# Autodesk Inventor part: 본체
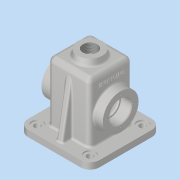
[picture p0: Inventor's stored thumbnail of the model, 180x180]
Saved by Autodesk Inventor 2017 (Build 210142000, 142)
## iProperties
Part Number: 본체
Material: 알루미늄 6061
Document SubType Name: Modeling
Designer: MRC
Density: 2.7 g/cm^3
Appearance: 알루미늄 - 평지
Mass: 753.623 g
Surface Area: 864.209 cm^2
Volume: 279.12 cm^3
Author: MRC
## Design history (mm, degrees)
sketch "스케치1"
  geometry: L1 (-34, 53)-(34, 53); L2 (34, 53)-(34, -52); L3 (34, -52)-(-34, -52); L4 (-34, -52)-(-34, 53); 2 further points
  constraints: 8 end point, 2 parallel, 1 horizontal, 1 midpoint, 1 perpendicular, 1 vertical alignment
  dimensions: "d0" = 52 distance from line of L3 point (0, 0); "d1" = 105 distance of L3.end L1.start; "d2" = 68 distance of L1.start L1.end
extrude "돌출1" new body sketch "스케치1" stored distance "d3" = 68; taper "d4" = 0 deg
fillet "모깎기1" dims "d5" = 8
fillet "모깎기2" dims "d6" = 8
feature "쉘1" dims "d7" = 5
sketch "스케치3"
  geometry: C1 r 28.5 at (26, 52); 1 further point
  constraints: 1 centre point, 1 coincident
  dimensions: "d8" = 57 diameter of C1
extrude "돌출2" join sketch "스케치3" distance "d9" = 15; taper "d11" = 0 deg; dims "d10" = 3, "d12" = 0
hole "구멍1" diameter "d15" = 30; stored, may be unused: countersink angle "d19" = 90 deg, drill point angle "d21" = 118 deg; dims "d13" = 10, "d14" = 10, "d16" = 6, "d17" = 35, "d18" = 17, "d20" = 30
sketch "스케치4"
  geometry: C1 r 17.5 at (0, 0) reference; 1 further point
  constraints: 1 vertical alignment
  dimensions: "d22" = 22 distance of C1.centre point (0, 22)
hole "구멍2" sketch "스케치4" at (0, 22) diameter "d23" = 3.242; stored, may be unused: countersink angle "d27" = 90 deg, drill point angle "d29" = 118 deg; dims "d24" = 8, "d25" = 35, "d26" = 17, "d28" = 10
sketch "스케치6"
  geometry: L1 (-8, 60)-(-8, 8) reference; L2 (52, 0)-(0, 0) reference; L3 (60, 60)-(60, 8) reference; L4 (0, 68)-(52, 68) reference; L5 (83, -23)-(-31, -23); L6 (-31, -23)-(-31, 91); L7 (-31, 91)-(83, 91); L8 (83, 91)-(83, -23); L9 (83, -23)-(-31, 91); L10 (-31, -23)-(83, 91); A1 r 8 centre (0, 60) between (0, 68) and (-8, 60) reference; A2 r 8 centre (0, 8) between (-8, 8) and (0, 0) reference; A3 r 8 centre (52, 8) between (52, 0) and (60, 8) reference; A4 r 8 centre (52, 60) between (60, 60) and (52, 68) reference; 1 further point
  constraints: 12 end point, 2 midpoint, 2 parallel, 1 horizontal, 1 perpendicular
  dimensions: "d45" = 114 distance of L6.end L7.end; "d46" = 114 distance of L5.end L6.end
extrude "돌출4" join sketch "스케치6" distance "d47" = 10; taper "d48" = 0 deg
fillet "모깎기3" dims "d49" = 15
sketch "스케치7"
  geometry: A1 r 15 centre (-16, 8) between (-16, 23) and (-31, 8) reference; A2 r 15 centre (-16, -76) between (-31, -76) and (-16, -91) reference; A3 r 15 centre (68, -76) between (68, -91) and (83, -76) reference; A4 r 15 centre (68, 8) between (83, 8) and (68, 23) reference; 5 further points
  constraints: 4 coincident
hole "구멍4" sketch "스케치7" at (-16, 8), (68, 8), (68, -76), (-16, -76) diameter "d50" = 10; stored, may be unused: countersink angle "d54" = 90 deg, drill point angle "d56" = 118 deg; dims "d51" = 50, "d52" = 18, "d53" = 2, "d55" = 59.3
sketch "스케치8"
  geometry: L1 (45, -34)-(-42, -34) reference; L2 (-42, -33)-(-42, -51) reference; L3 (-42, -42)-(-42, -57) reference; L4 (43.069, -34)-(-42, -49); L5 (-42, -57)-(-52, -57) reference; 1 further point
  constraints: 2 end point, 2 point on line
  dimensions: "d57" = 8 distance of L4.end L3.end; "d58" = 10 deg angle of L5 L4
feature "리브1" sketch "스케치8" dims "d59" = 1, "d60" = 10, "d61" = 0, "d62" = 0, "d63" = 1, "d64" = 1
sketch "스케치9"
  geometry: L1 (-8, 0)-(-8, -87) reference; L2 (46, 18)-(6, 18) reference; 1 further point
  constraints: 1 other
  dimensions: "d65" = 34 distance from line of L1 point (26, -7); "d66" = 25 distance from line of L2 point (26, -7)
feature "엠보싱1" sketch "스케치9" dims "d0" = 52, "d1" = 105, "d2" = 68, "d8" = 57, "d67" = 0.5, "d68" = 0
fillet "모깎기4" dims "d69" = 3
fillet "모깎기5" dims "d70" = 3
fillet "모깎기6" dims "d71" = 3
chamfer "모따기1" distance "d72" = 1; stored, may be unused: second distance "d73" = 2, angle "d74" = 45 deg
fillet "모깎기7" dims "d75" = 0.3
node "작업 평면1"
sketch "스케치10"
  geometry: C1 r 20 at (-42, 57); 1 further point
  constraints: 1 centre point, 1 coincident
  dimensions: "d77" = 40 diameter of C1
extrude "돌출5" join sketch "스케치10" stored distance "d78" = 40 (= d77); taper "d79" = 8 deg
hole "구멍5" diameter "d82" = 22.835; stored, may be unused: countersink angle "d86" = 90 deg, drill point angle "d88" = 118 deg; dims "d80" = 10, "d81" = 10, "d83" = 50, "d84" = 18, "d85" = 2, "d87" = 59.3
fillet "모깎기8" dims "d89" = 3
node "솔리드1"
pattern_circular "원형 패턴1" dims angle "d31" = 360 deg
mirror "미러1"
mirror "미러2"
other parameters: "d76" = -115
